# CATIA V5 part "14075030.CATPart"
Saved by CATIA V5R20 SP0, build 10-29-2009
Part number: 14075030
Definition: NONE
Nomenclature: 14075030
Source: Unknown
Description: 14075030
Bounding box of the stored display mesh (mm): x -15 to 60, y -51.5 to 41.58, z -41.6 to 41.6
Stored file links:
  C:\Users\Utente\Desktop\IO LAVORO\3D X SITO CF\X SITO\PLASTICA\RF2\14075030.CATPart
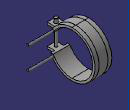
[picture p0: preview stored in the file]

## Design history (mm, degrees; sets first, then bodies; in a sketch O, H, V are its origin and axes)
Body1 "14075030" (main body)
  Solid1: solid without history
